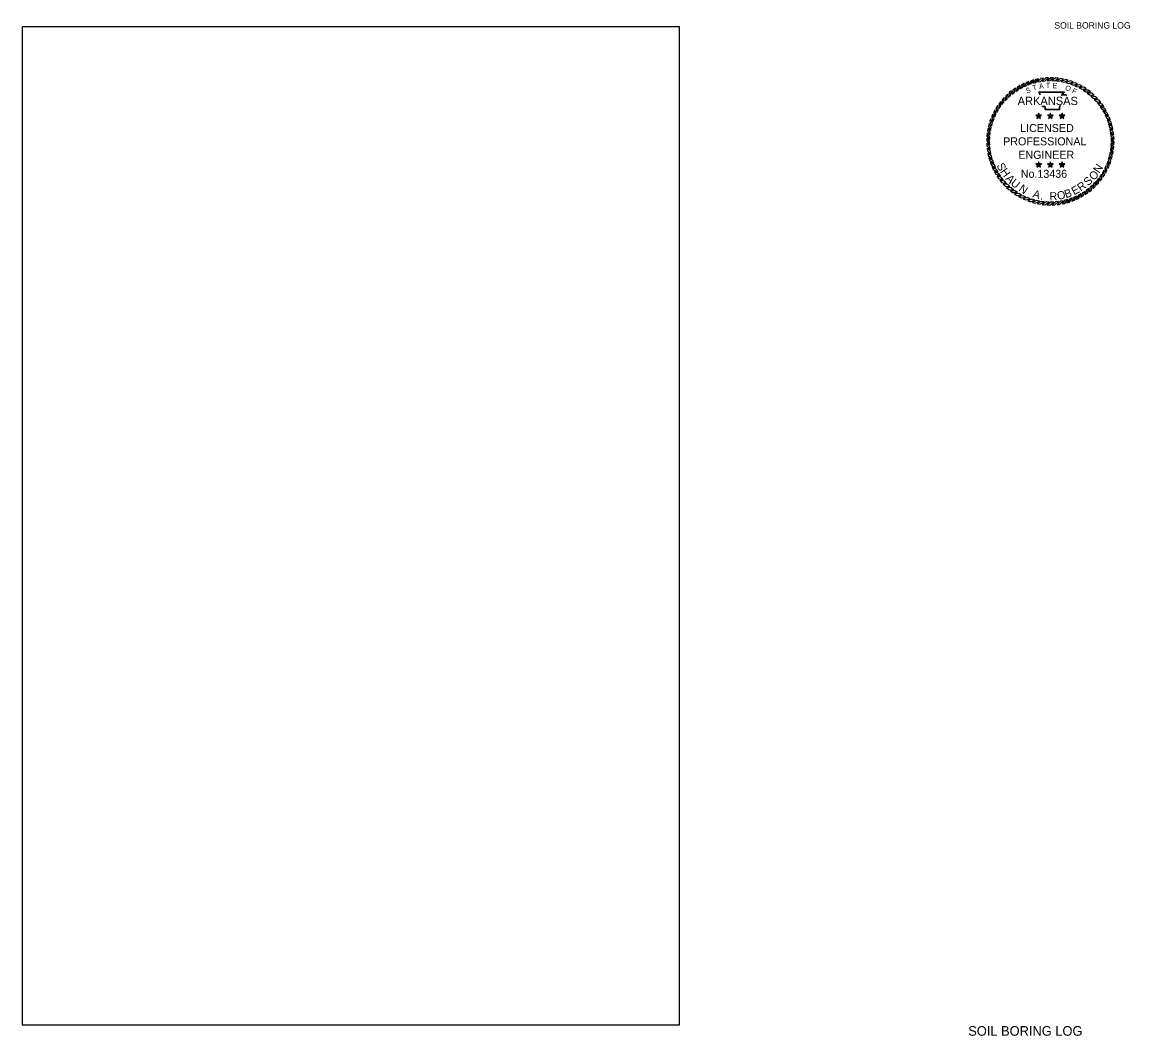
# Model space of a CAD drawing. Extents: x 987302 to 990833, y 1868293 to 1870149.
import ezdxf

# ---------------------------------------------------------------- set-up
doc = ezdxf.new("R2010")
doc.units = 0
for name, color, linetype in [('1', 7, 'Continuous'), ('60', 7, 'Continuous'), ('Default', 7, 'Continuous'), ('G-ANNO-SYMB', 7, 'Continuous')]:
    doc.layers.add(name, color=color, linetype=linetype)

msp = doc.modelspace()

# ---------------------------------------------------------------- linework, layer by layer
at = {"layer": 'Default'}
msp.add_lwpolyline([(989795, 1868666), (990410.6, 1868666), (990410.6, 1869600.9), (989795, 1869600.9)], close=True, dxfattribs=at)
at = {"layer": 'G-ANNO-SYMB'}
for points in [[(990751.8, 1869553.1), (990749.2, 1869552.7), (990746.1, 1869549.4), (990748.8, 1869549.9)], [(990756.4, 1869553.4), (990753.9, 1869553.2), (990750.5, 1869550.2), (990753.3, 1869550.5)], [(990761.1, 1869553.3), (990758.6, 1869553.4), (990755, 1869550.6), (990757.7, 1869550.7)], [(990765.8, 1869552.9), (990763.2, 1869553.2), (990759.4, 1869550.7), (990762.2, 1869550.5)], [(990770.4, 1869552.1), (990767.9, 1869552.6), (990763.9, 1869550.4), (990766.6, 1869550)], [(990725.5, 1869543.7), (990723.4, 1869542.2), (990722.2, 1869537.9), (990724.3, 1869539.6)], [(990729.5, 1869546.1), (990727.3, 1869544.8), (990725.7, 1869540.5), (990728, 1869542.1)], [(990733.7, 1869548.2), (990731.4, 1869547.1), (990729.5, 1869542.9), (990731.9, 1869544.3)], [(990738.1, 1869549.9), (990735.7, 1869549), (990733.4, 1869545), (990736, 1869546.2)], [(990742.6, 1869551.3), (990740.1, 1869550.6), (990737.5, 1869546.8), (990740.2, 1869547.8)], [(990747.1, 1869552.4), (990744.6, 1869551.8), (990741.8, 1869548.3), (990744.4, 1869549)], [(990774.9, 1869551), (990772.5, 1869551.7), (990768.3, 1869549.8), (990771, 1869549.2)], [(990779.4, 1869549.5), (990777, 1869550.4), (990772.7, 1869548.8), (990775.3, 1869548)], [(990783.7, 1869547.6), (990781.4, 1869548.7), (990776.9, 1869547.5), (990779.5, 1869546.5)], [(990787.8, 1869545.5), (990785.6, 1869546.7), (990781.1, 1869545.8), (990783.6, 1869544.7)], [(990791.8, 1869543), (990789.7, 1869544.4), (990785.1, 1869543.9), (990787.5, 1869542.5)], [(990714.8, 1869534.7), (990713, 1869532.8), (990712.8, 1869528.2), (990714.6, 1869530.4)], [(990718.1, 1869538), (990716.3, 1869536.2), (990715.7, 1869531.7), (990717.6, 1869533.7)], [(990721.7, 1869541), (990719.7, 1869539.4), (990718.8, 1869534.9), (990720.9, 1869536.8)], [(990795.6, 1869540.2), (990793.5, 1869541.8), (990789, 1869541.6), (990791.3, 1869540)], [(990799.1, 1869537.1), (990797.2, 1869538.8), (990792.6, 1869539), (990794.8, 1869537.3)], [(990802.4, 1869533.8), (990800.6, 1869535.6), (990796.1, 1869536.2), (990798.1, 1869534.3)], [(990805.4, 1869530.2), (990803.8, 1869532.2), (990799.3, 1869533.1), (990801.2, 1869531)], [(990706.4, 1869523.4), (990705.2, 1869521.2), (990706, 1869516.7), (990707.2, 1869519.2)], [(990708.9, 1869527.4), (990707.5, 1869525.3), (990708, 1869520.7), (990709.4, 1869523.1)], [(990711.7, 1869531.2), (990710.1, 1869529.1), (990710.3, 1869524.6), (990711.8, 1869526.9)], [(990808.1, 1869526.4), (990806.7, 1869528.5), (990802.3, 1869529.7), (990804, 1869527.5)], [(990810.5, 1869522.3), (990809.2, 1869524.6), (990804.9, 1869526.2), (990806.5, 1869523.8)], [(990812.6, 1869518.1), (990811.5, 1869520.5), (990807.3, 1869522.4), (990808.7, 1869520)], [(990702.4, 1869515), (990701.5, 1869512.6), (990703.1, 1869508.3), (990703.9, 1869510.9)], [(990704.2, 1869519.3), (990703.2, 1869517), (990704.4, 1869512.5), (990705.4, 1869515.1)], [(990747.2, 1869517.5), (990746.6, 1869518.3), (990744.6, 1869518.3), (990746.2, 1869517.2)], [(990747.2, 1869517.5), (990746.2, 1869517.2), (990745.6, 1869515.3), (990747.2, 1869516.5)], [(990747.2, 1869517.5), (990747.8, 1869518.3), (990747.2, 1869520.2), (990746.6, 1869518.3)], [(990747.2, 1869517.5), (990748.2, 1869517.2), (990749.8, 1869518.3), (990747.8, 1869518.3)], [(990747.2, 1869517.5), (990747.2, 1869516.5), (990748.8, 1869515.3), (990748.2, 1869517.2)], [(990758.1, 1869517.5), (990757.5, 1869518.3), (990755.5, 1869518.3), (990757.2, 1869517.2)], [(990758.1, 1869517.5), (990757.2, 1869517.2), (990756.5, 1869515.3), (990758.1, 1869516.5)], [(990758.1, 1869517.5), (990758.8, 1869518.3), (990758.1, 1869520.2), (990757.5, 1869518.3)], [(990758.1, 1869517.5), (990759.1, 1869517.2), (990760.7, 1869518.3), (990758.8, 1869518.3)], [(990758.1, 1869517.5), (990758.1, 1869516.5), (990759.7, 1869515.3), (990759.1, 1869517.2)], [(990769.1, 1869517.5), (990768.4, 1869518.3), (990766.5, 1869518.3), (990768.1, 1869517.2)], [(990769.1, 1869517.5), (990768.1, 1869517.2), (990767.4, 1869515.3), (990769.1, 1869516.5)], [(990769.1, 1869517.5), (990769.7, 1869518.3), (990769.1, 1869520.2), (990768.4, 1869518.3)], [(990769.1, 1869517.5), (990770, 1869517.2), (990771.6, 1869518.3), (990769.7, 1869518.3)], [(990769.1, 1869517.5), (990769.1, 1869516.5), (990770.7, 1869515.3), (990770, 1869517.2)], [(990814.3, 1869513.8), (990813.4, 1869516.2), (990809.4, 1869518.4), (990810.6, 1869515.9)], [(990815.7, 1869509.3), (990815, 1869511.8), (990811.2, 1869514.3), (990812.2, 1869511.7)], [(990699, 1869501.4), (990698.7, 1869498.8), (990701.2, 1869495), (990701.4, 1869497.8)], [(990699.8, 1869506), (990699.3, 1869503.5), (990701.5, 1869499.5), (990701.8, 1869502.2)], [(990700.9, 1869510.5), (990700.2, 1869508.1), (990702.1, 1869503.9), (990702.7, 1869506.6)], [(990816.8, 1869504.8), (990816.2, 1869507.3), (990812.7, 1869510.1), (990813.4, 1869507.4)], [(990817.5, 1869500.1), (990817.1, 1869502.7), (990813.8, 1869505.8), (990814.3, 1869503.1)], [(990817.8, 1869495.4), (990817.6, 1869498), (990814.6, 1869501.4), (990814.9, 1869498.6)], [(990698.6, 1869496.7), (990698.5, 1869494.2), (990701.3, 1869490.6), (990701.2, 1869493.3)], [(990698.5, 1869492), (990698.6, 1869489.5), (990701.7, 1869486.1), (990701.4, 1869488.9)], [(990817.3, 1869486.1), (990817.6, 1869488.6), (990815.1, 1869492.5), (990814.9, 1869489.7)], [(990817.7, 1869490.8), (990817.8, 1869493.3), (990815, 1869496.9), (990815.1, 1869494.2)], [(990698.8, 1869487.4), (990699.2, 1869484.8), (990702.5, 1869481.7), (990702, 1869484.4)], [(990699.5, 1869482.7), (990700, 1869480.2), (990703.6, 1869477.4), (990702.9, 1869480)], [(990815.4, 1869476.9), (990816.1, 1869479.4), (990814.2, 1869483.6), (990813.6, 1869480.9)], [(990816.5, 1869481.5), (990817, 1869484), (990814.8, 1869488), (990814.4, 1869485.2)], [(990700.6, 1869478.2), (990701.3, 1869475.7), (990705.1, 1869473.1), (990704.1, 1869475.7)], [(990702, 1869473.7), (990702.9, 1869471.3), (990706.8, 1869469), (990705.7, 1869471.6)], [(990747.2, 1869471.8), (990746.6, 1869472.7), (990744.6, 1869472.7), (990746.2, 1869471.5)], [(990747.2, 1869471.8), (990746.2, 1869471.5), (990745.6, 1869469.6), (990747.2, 1869470.8)], [(990747.2, 1869471.8), (990747.8, 1869472.7), (990747.2, 1869474.5), (990746.6, 1869472.7)], [(990747.2, 1869471.8), (990748.2, 1869471.5), (990749.8, 1869472.7), (990747.8, 1869472.7)], [(990747.2, 1869471.8), (990747.2, 1869470.8), (990748.8, 1869469.6), (990748.2, 1869471.5)], [(990758.1, 1869471.8), (990757.5, 1869472.7), (990755.5, 1869472.7), (990757.2, 1869471.5)], [(990758.1, 1869471.8), (990757.2, 1869471.5), (990756.5, 1869469.6), (990758.1, 1869470.8)], [(990758.1, 1869471.8), (990758.8, 1869472.7), (990758.1, 1869474.5), (990757.5, 1869472.7)], [(990758.1, 1869471.8), (990759.1, 1869471.5), (990760.7, 1869472.7), (990758.8, 1869472.7)], [(990758.1, 1869471.8), (990758.1, 1869470.8), (990759.7, 1869469.6), (990759.1, 1869471.5)], [(990769.1, 1869471.8), (990768.4, 1869472.7), (990766.5, 1869472.7), (990768.1, 1869471.5)], [(990769.1, 1869471.8), (990768.1, 1869471.5), (990767.4, 1869469.6), (990769.1, 1869470.8)], [(990769.1, 1869471.8), (990769.7, 1869472.7), (990769.1, 1869474.5), (990768.4, 1869472.7)], [(990769.1, 1869471.8), (990770, 1869471.5), (990771.6, 1869472.7), (990769.7, 1869472.7)], [(990769.1, 1869471.8), (990769.1, 1869470.8), (990770.7, 1869469.6), (990770, 1869471.5)], [(990809.9, 1869464), (990811.1, 1869466.3), (990810.2, 1869470.8), (990809.1, 1869468.3)], [(990812.1, 1869468.2), (990813.1, 1869470.5), (990811.9, 1869474.9), (990810.9, 1869472.3)], [(990813.9, 1869472.5), (990814.8, 1869474.9), (990813.2, 1869479.2), (990812.4, 1869476.5)], [(990703.7, 1869469.3), (990704.8, 1869467), (990708.9, 1869465.1), (990707.6, 1869467.5)], [(990705.8, 1869465.1), (990707.1, 1869462.9), (990711.3, 1869461.3), (990709.8, 1869463.6)], [(990708.2, 1869461.1), (990709.6, 1869459), (990714, 1869457.7), (990712.3, 1869459.9)], [(990801.5, 1869452.8), (990803.2, 1869454.7), (990803.4, 1869459.2), (990801.7, 1869457.1)], [(990804.6, 1869456.3), (990806.2, 1869458.3), (990806, 1869462.9), (990804.4, 1869460.6)], [(990807.4, 1869460.1), (990808.8, 1869462.2), (990808.3, 1869466.8), (990806.9, 1869464.4)], [(990710.9, 1869457.3), (990712.5, 1869455.3), (990717, 1869454.4), (990715.1, 1869456.4)], [(990713.9, 1869453.7), (990715.7, 1869451.8), (990720.2, 1869451.3), (990718.2, 1869453.2)], [(990717.2, 1869450.4), (990719.1, 1869448.6), (990723.7, 1869448.4), (990721.5, 1869450.2)], [(990790.8, 1869443.8), (990792.9, 1869445.2), (990794.1, 1869449.6), (990791.9, 1869447.9)], [(990794.6, 1869446.5), (990796.6, 1869448.1), (990797.5, 1869452.6), (990795.4, 1869450.7)], [(990798.2, 1869449.5), (990800, 1869451.3), (990800.6, 1869455.8), (990798.7, 1869453.8)], [(990720.7, 1869447.3), (990722.7, 1869445.7), (990727.3, 1869445.9), (990725, 1869447.4)], [(990724.5, 1869444.5), (990726.6, 1869443.1), (990731.2, 1869443.6), (990728.8, 1869445)], [(990728.4, 1869442), (990730.7, 1869440.8), (990735.2, 1869441.6), (990732.7, 1869442.8)], [(990732.6, 1869439.8), (990734.9, 1869438.8), (990739.3, 1869440), (990736.7, 1869441)], [(990736.9, 1869438), (990739.3, 1869437.1), (990743.6, 1869438.7), (990740.9, 1869439.5)], [(990769.2, 1869435.1), (990771.7, 1869435.6), (990774.5, 1869439.2), (990771.8, 1869438.5)], [(990773.7, 1869436.2), (990776.2, 1869436.9), (990778.7, 1869440.7), (990776.1, 1869439.7)], [(990778.2, 1869437.6), (990780.6, 1869438.5), (990782.8, 1869442.4), (990780.3, 1869441.3)], [(990782.5, 1869439.3), (990784.9, 1869440.4), (990786.8, 1869444.5), (990784.4, 1869443.2)], [(990786.7, 1869441.4), (990789, 1869442.7), (990790.6, 1869446.9), (990788.2, 1869445.4)], [(990741.3, 1869436.5), (990743.8, 1869435.8), (990748, 1869437.7), (990745.3, 1869438.3)], [(990745.9, 1869435.4), (990748.4, 1869434.9), (990752.4, 1869437.1), (990749.6, 1869437.4)], [(990750.5, 1869434.6), (990753, 1869434.3), (990756.9, 1869436.8), (990754.1, 1869437)], [(990755.2, 1869434.2), (990757.7, 1869434.1), (990761.3, 1869436.9), (990758.6, 1869436.8)], [(990759.8, 1869434.1), (990762.4, 1869434.2), (990765.8, 1869437.3), (990763, 1869437)], [(990764.5, 1869434.4), (990767.1, 1869434.8), (990770.2, 1869438.1), (990767.5, 1869437.6)]]:
    msp.add_lwpolyline(points, close=True, dxfattribs=at)
for points in [[(990748.6, 1869537), (990747.2, 1869540.1), (990771.3, 1869540.1), (990769.2, 1869537.5), (990770.9, 1869537.6), (990772.2, 1869537.6), (990773.6, 1869537.4)], [(990748.9, 1869537.2), (990747.8, 1869539.7), (990770.5, 1869539.7), (990768.4, 1869537.1), (990770.9, 1869537.2), (990772.2, 1869537.2), (990773.6, 1869537.1)], [(990767.5, 1869527), (990767.1, 1869526.6), (990766.9, 1869526.1), (990766.8, 1869524.9), (990766.8, 1869523.2), (990753.3, 1869523.2), (990753.3, 1869525.5), (990753.3, 1869526), (990752.8, 1869526.1), (990750.9, 1869526.1), (990750.6, 1869526.6)], [(990767.2, 1869527.3), (990766.7, 1869526.8), (990766.5, 1869526.2), (990766.4, 1869524.9), (990766.4, 1869523.6), (990753.7, 1869523.6), (990753.7, 1869525.5), (990753.7, 1869526.2), (990752.9, 1869526.5), (990751.1, 1869526.5), (990750.9, 1869526.8)]]:
    msp.add_lwpolyline(points, dxfattribs=at)

# ---------------------------------------------------------------- texts
at = {"layer": '1'}
msp.add_text('SOIL BORING LOG', height=6, rotation=360, dxfattribs=at).set_placement((990761.9, 1869599.4))
at = {"layer": '60'}
msp.add_text('SOIL BORING LOG', height=9, rotation=360, dxfattribs=at).set_placement((990681.2, 1868655.7))
at = {"layer": 'G-ANNO-SYMB'}
for s, height, rotation, p in [('S', 4.75, 19.7726, (990736.1, 1869538.6)), ('T', 4.75, 16.9015, (990742.1, 1869541.3)), ('A', 4.75, 8.6788, (990747.9, 1869542.8)), ('T', 4.75, 1.4789, (990754, 1869543.8)), ('E', 4.75, 356.672, (990760.1, 1869543.6)), ('O', 4.75, 341.2218, (990771.6, 1869542)), ('F', 4.75, 335.3628, (990778, 1869539.5)), ('S', 7.5, 298.1636, (990707.5, 1869471.1)), ('N', 7.5, 56.1007, (990803.9, 1869463.3)), ('H', 7.5, 305.619, (990710.9, 1869465.3)), ('A', 7.5, 313.4472, (990715.6, 1869458.4)), ('S', 7.5, 43.4878, (990793.5, 1869451.6)), ('O', 7.5, 44.7757, (990798.7, 1869456.6)), ('U', 7.5, 320.9026, (990720.3, 1869453.5)), ('N', 7.5, 324.9326, (990727.9, 1869447.9)), ('B', 7.5, 18.885, (990772.7, 1869440.4)), ('E', 7.5, 27.8315, (990780.3, 1869443.2)), ('R', 7.5, 35.6597, (990786.6, 1869446.5)), ('A', 7.5, 343.0991, (990741, 1869441.5)), ('.', 7.5, 351.3, (990748.3, 1869439.3)), ('R', 7.5, 3.2287, (990757.5, 1869438.4)), ('O', 7.5, 11.4296, (990765.2, 1869438.9))]:
    msp.add_text(s, height=height, rotation=rotation, dxfattribs=at).set_placement(p)
for s, height, p in [('ARKANSAS', 7.75, (990727.5, 1869527.8)), ('LICENSED', 7.5, (990729.9, 1869502.5)), ('PROFESSIONAL', 7.5, (990713.9, 1869490)), ('ENGINEER', 7.5, (990728.1, 1869477.4)), ('No.13436', 7.47, (990730.5, 1869459.6))]:
    msp.add_text(s, height=height, dxfattribs=at).set_placement(p)

doc.saveas('drawing.dxf')
